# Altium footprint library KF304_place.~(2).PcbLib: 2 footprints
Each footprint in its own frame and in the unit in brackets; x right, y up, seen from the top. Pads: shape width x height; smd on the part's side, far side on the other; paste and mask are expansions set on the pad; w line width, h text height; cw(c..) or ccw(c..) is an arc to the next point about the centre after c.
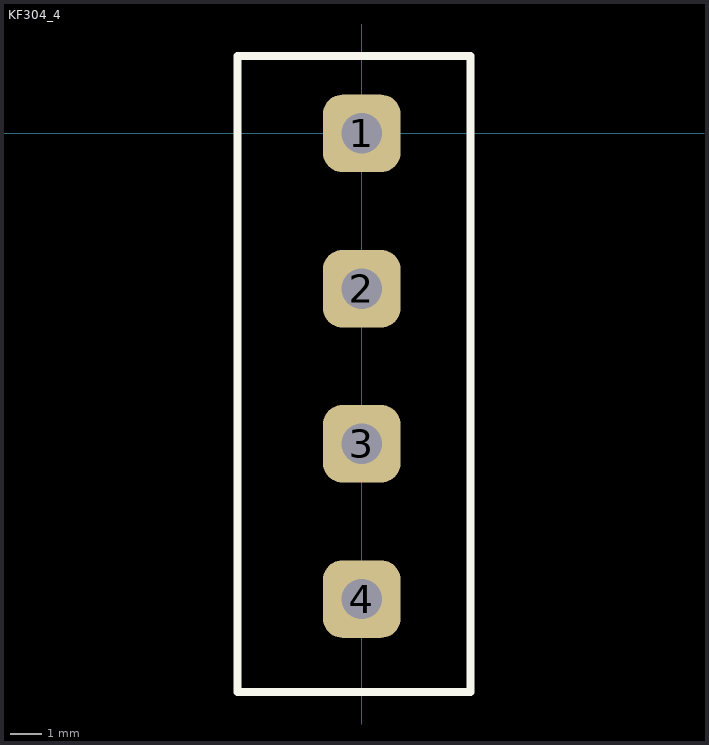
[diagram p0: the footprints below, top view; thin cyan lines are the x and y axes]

## KF304_4 [mm]
height 14.5
pads (4):
  rrect50% 2.5x2.5 hole 1.3 paste+0 mask+0.102: 1(0,0) 2(0,-5) 3(0,-10) 4(0,-15)
Top Overlay:
  lines w0.254: -4,-18 3.5,-18 3.5,2.5 -4,2.5 -4,-18

## PCBComponent_1 [mm]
